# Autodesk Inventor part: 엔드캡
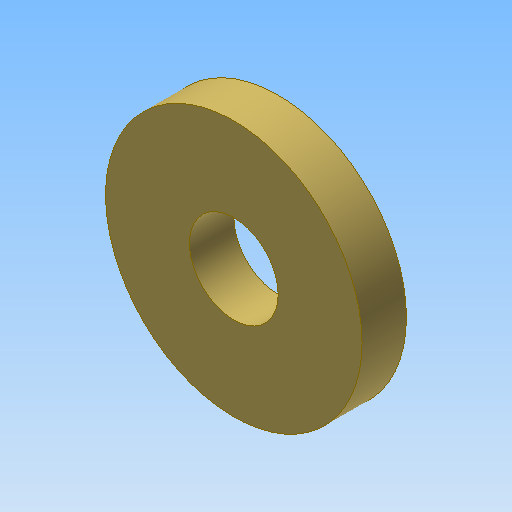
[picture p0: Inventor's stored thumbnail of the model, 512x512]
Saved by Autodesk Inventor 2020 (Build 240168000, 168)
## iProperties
Created: 2023-03
Part Number: 엔드캡
Material: 강철, 연강
Document SubType Name: Modeling
Designer: mdu-01
Density: 1 g/cm^3
Appearance: 기본값(1)
Author: mdu-01
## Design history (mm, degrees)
sketch "스케치1"
  geometry: C1 r 13 at (0, 0); 1 further point
  constraints: 1 centre point, 1 coincident
  dimensions: "d0" = 26 diameter of C1
extrude "돌출1" new body sketch "스케치1" distance "d1" = 4.5; taper "d2" = 0 deg
hole "구멍1" diameter "d6" = 9; stored, may be unused: countersink angle "d10" = 90 deg, drill point angle "d12" = 118 deg; dims "d4" = 10, "d5" = 10, "d7" = 6, "d8" = 17.3, "d9" = 2, "d11" = 8
node "솔리드1"
